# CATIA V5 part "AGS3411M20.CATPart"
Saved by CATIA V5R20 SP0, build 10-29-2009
Part number: AGS3411M20
Definition: NONE
Nomenclature: AGS3411M20
Source: Unknown
Description: AGS3411M20
Bounding box of the stored display mesh (mm): x -35 to 33, y -17.347 to 17.347, z -14 to 14
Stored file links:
  C:\Users\Utente\Desktop\IO LAVORO\3D X SITO CF\X SITO\PLASTICA\AGS\AGS3411M20.CATPart
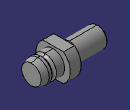
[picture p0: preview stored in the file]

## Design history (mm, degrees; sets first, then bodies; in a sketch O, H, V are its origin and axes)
Body1 "AGS3411M20" (main body)
  Solid1: solid without history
